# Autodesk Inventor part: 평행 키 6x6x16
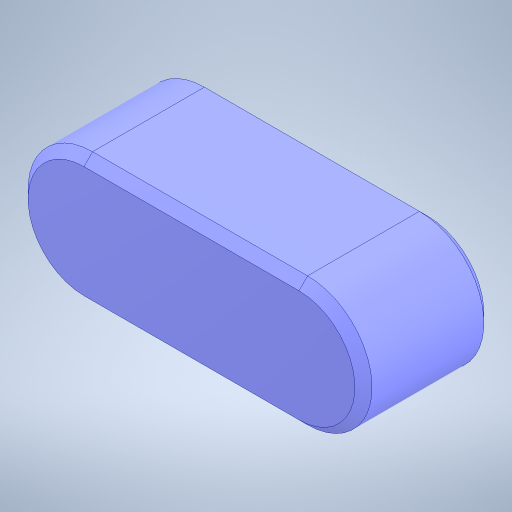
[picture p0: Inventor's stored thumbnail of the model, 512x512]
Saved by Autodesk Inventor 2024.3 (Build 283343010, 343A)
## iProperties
Created: 2025-11
Part Number: 평행 키 6x6x16
Material: 강철, 연강
Description: 키 및 해당 키홈
Document SubType Name: Modeling
Designer: PC2-15
Density: 7.85 g/cm^3
Appearance: 기본값
Author: jhkim
Sending System: Autodesk Inventor 2026
Preprocessor: ST-DEVELOPER v20.1
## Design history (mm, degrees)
node "평행 키 6x6x161"
node "솔리드1"
body "Solid1"
